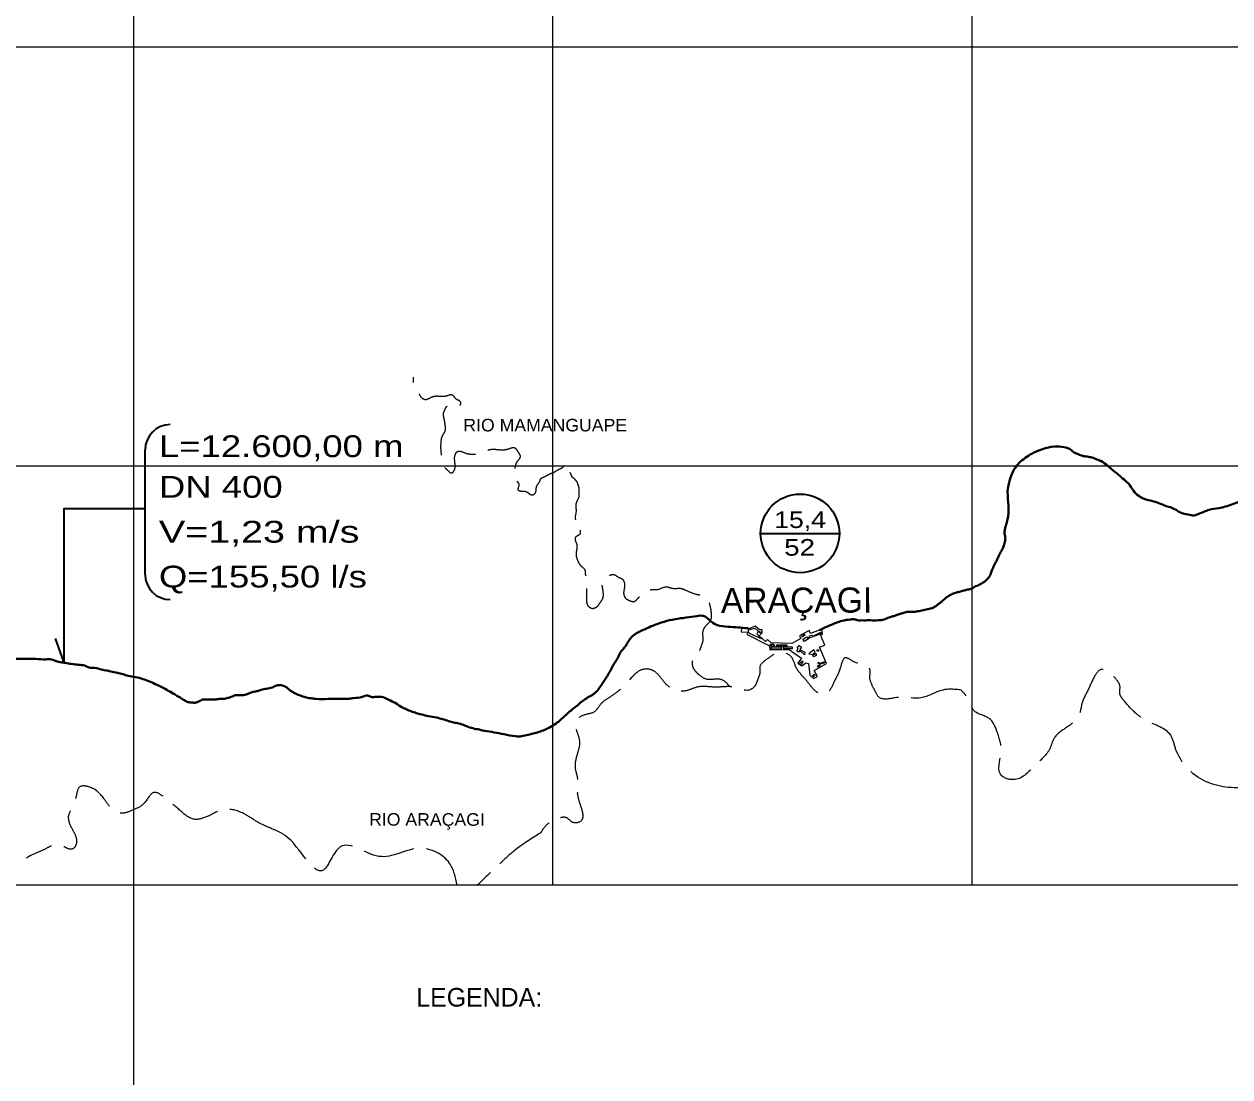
# Model space of a CAD drawing. Extents: x 0 to 1772, y 0 to 1188.
# Drawn here: x 598.6 to 781.9, y 161 to 321.1 of the extents above; entities that cross this region are included whole.
import ezdxf
from ezdxf.enums import TextEntityAlignment as Align

# ---------------------------------------------------------------- set-up
doc = ezdxf.new("R2010")
doc.units = 0
doc.header["$LTSCALE"] = 1.3
doc.linetypes.add('DOT_DASHED', pattern=[7.7, 5, -1.2, 0.3, -1.2])
doc.linetypes.add('LONG_DASHED', pattern=[7.5, 6, -1.5])
for name, color, linetype, lineweight in [('1', 7, 'DOT_DASHED', 13), ('5', 7, 'LONG_DASHED', 25), ('6', 7, 'Continuous', 40), ('63', 7, 'Continuous', 25), ('8', 7, 'Continuous', 35), ('9', 7, 'Continuous', 40)]:
    doc.layers.add(name, color=color, linetype=linetype, lineweight=lineweight)

msp = doc.modelspace()

# ---------------------------------------------------------------- linework, layer by layer
at = {"layer": '1', "linetype": 'Continuous'}
for points in [[(720.533, 223.884), (719.503, 226.352), (720.286, 226.679), (719.65, 228.204), (719.93, 228.321), (719.842, 229.095), (718.089, 228.414), (717.909, 228.876), (716.432, 228.061), (716.644, 227.677), (715.289, 226.93), (712.115, 227.006), (711.554, 227.526), (711.257, 227.205), (710.317, 228.077), (710.755, 228.55), (710.759, 228.971), (710.337, 228.975), (709.716, 229.547), (708.753, 229.12), (707.614, 229.213), (707.572, 228.692), (708.513, 228.615), (708.485, 228.274), (711.885, 226.561), (711.906, 225.924), (714.853, 226.022), (715.591, 225.51), (716.764, 224.695), (716.209, 223.896), (716.779, 223.501), (717.427, 223.971), (717.794, 223.876), (717.992, 222.119), (718.592, 221.58), (719.169, 221.891), (718.676, 222.809)], [(708.709, 228.614), (708.708, 228.97), (709.645, 229.26), (710.11, 228.816), (710.615, 228.581), (710.571, 228.487), (710.123, 228.697), (709.979, 228.39), (710.687, 227.622), (708.917, 228.398)], [(716.855, 227.902), (717.319, 228.183), (717.221, 228.345), (716.757, 228.064)], [(719.723, 228.403), (718.011, 227.773), (717.189, 227.212), (716.971, 227.531), (717.519, 227.905), (717.65, 227.712), (718.002, 227.952), (717.91, 228.086), (718.302, 228.186), (718.542, 228.094), (719.669, 228.615)], [(712.645, 226.501), (712.279, 226.5), (711.983, 226.657), (712.066, 226.815), (712.555, 226.797)], [(712.093, 226.104), (713.712, 226.109), (713.711, 226.346), (712.092, 226.341)], [(714.579, 226.675), (712.96, 226.67), (712.96, 226.482), (714.58, 226.487)], [(713.978, 226.159), (715.39, 226.164), (715.389, 226.341), (713.978, 226.337)], [(716.509, 225.867), (716.299, 225.589), (716.021, 225.798), (716.231, 226.077), (716.08, 226.19), (716.412, 226.631), (716.759, 226.37), (716.498, 226.023), (717.265, 225.611), (717.189, 225.199)], [(718.601, 225.959), (717.867, 225.364), (718.422, 225.232), (718.841, 225.587)], [(719.118, 225.75), (719.117, 225.964), (719.331, 225.965), (719.332, 225.751)], [(716.63, 223.677), (717.002, 224.051), (716.819, 224.232), (716.448, 223.858)], [(718.986, 225.08), (718.605, 224.869), (718.458, 225.133), (718.957, 225.409)], [(719.564, 223.58), (719.269, 223.33), (719.16, 223.459), (719.455, 223.709)], [(719.334, 223.771), (719.238, 223.962), (719.429, 224.058), (719.525, 223.867)], [(720.327, 224.032), (719.745, 223.753), (719.667, 223.915), (720.249, 224.194)], [(718.566, 221.865), (718.412, 222.036), (718.659, 222.257), (718.813, 222.085)]]:
    msp.add_lwpolyline(points, close=True, dxfattribs=at)
at = {"layer": '5'}
for points in [[(677.987, 252.401), (677.389, 252.097), (677.07, 251.93), (676.911, 251.53), (676.559, 250.992), (676.422, 250.712), (676.35, 250.134), (676.202, 249.707), (675.852, 249.458), (675.468, 249.581), (675.038, 249.89), (674.492, 250.041), (674.057, 250.04), (673.751, 250.173), (673.714, 250.548), (673.845, 251.107), (673.556, 251.51), (673.296, 251.966), (673.214, 252.781), (673.213, 253.141), (673.288, 253.972), (673.567, 254.593), (673.928, 255.067), (674.025, 255.41), (673.783, 255.866), (673.447, 256.403), (673.105, 256.643), (672.38, 256.527), (671.737, 256.353), (670.576, 256.35), (669.332, 256.346), (668.676, 256.114), (667.779, 255.843), (667.299, 255.657), (666.508, 255.655), (665.992, 255.724), (664.924, 256.08), (664.348, 256.003), (664.085, 255.656), (664.014, 254.461), (664.016, 253.477), (663.801, 253.021), (663.564, 252.79), (663.109, 253.094), (662.592, 253.615), (662.319, 254.28), (662.12, 255.135), (661.96, 256.268), (661.957, 257.415), (662.036, 258.101), (662.299, 258.699), (662.629, 259.379), (662.628, 259.815), (662.47, 260.869), (662.349, 261.98), (662.601, 262.566), (662.911, 263.036), (663.574, 263.037), (664.48, 263.04), (664.899, 263.227), (664.897, 263.662), (664.302, 264.035), (663.706, 264.657), (662.624, 264.498), (661.26, 264.494), (660.462, 264.316), (659.586, 263.972), (658.99, 264.302), (658.52, 265.027), (658.033, 265.706), (657.801, 266.239), (657.798, 267.405)], [(705.846, 220.321), (705.244, 221.014), (704.288, 221.478), (702.311, 221.472), (701.198, 222.136), (700.619, 222.713), (700.217, 223.445), (700.214, 224.357), (700.479, 225.047), (701.077, 225.516), (701.43, 226.273), (701.782, 227.408), (701.778, 228.72), (702.198, 229.589), (702.774, 230.191), (703.039, 230.725), (703.035, 231.748), (702.765, 232.97), (702.029, 233.991), (700.829, 234.343), (699.205, 234.961), (698.383, 235.248), (697.228, 235.244), (696.25, 235.486), (694.696, 235.059), (693.874, 235.056), (692.553, 234.305), (691.808, 233.71), (691.397, 233.296), (690.559, 233.422), (690.095, 233.692), (689.757, 234.568), (689.896, 235.728), (689.636, 236.579), (688.797, 237.028), (688.358, 237.323), (687.457, 237.165), (686.982, 236.79), (686.455, 236.249), (686.458, 235.44), (686.56, 234.668), (686.562, 233.986), (686.355, 233.467), (685.993, 232.948), (685.704, 232.529), (685.368, 232.301), (684.906, 232.208), (684.542, 232.398), (684.214, 232.834), (684.121, 233.588), (684.118, 234.551), (684.115, 235.379), (684.112, 236.588), (684.019, 237.151), (683.909, 237.487), (683.908, 237.923), (683.434, 238.522), (682.951, 239.093), (682.668, 239.756), (682.53, 240.282), (682.627, 241.274), (682.625, 241.989), (682.405, 242.571), (682.48, 243.148), (683.087, 243.573), (683.084, 244.669), (683.082, 245.38), (682.511, 245.673), (682.508, 246.839), (682.504, 248.092), (682.72, 248.718), (682.947, 249.251), (682.945, 249.84), (682.943, 250.533), (682.831, 250.929), (682.675, 251.393), (682.439, 251.715), (682.116, 252.048), (681.942, 252.165), (681.753, 252.546), (681.564, 252.96), (681.43, 253.319), (681.149, 253.646), (681.071, 253.974), (681.02, 254.197), (680.673, 253.957), (680.417, 253.663), (679.759, 253.309), (679.161, 252.936), (678.517, 252.677), (677.987, 252.401)], [(878.537, 228.689), (877.747, 230.803), (877.216, 232.856), (877.212, 234.145), (875.304, 234.14), (873.443, 234.134), (870.863, 235.13), (868.856, 236.127), (866.699, 235.399), (864.745, 233.881), (862.487, 231.228), (860.772, 228.743), (859.528, 226.282), (858.189, 224.317), (856.519, 222.611), (851.453, 222.861), (846.687, 222.847), (842.65, 222.567), (841.119, 222.222), (837.914, 222.032), (836.297, 223.062), (835.291, 226.072), (833.291, 228.044), (831.386, 228.438), (828.195, 227.04), (824.327, 224.014), (819.287, 222.831), (815.491, 221.162), (811.543, 219.831), (808.084, 218.691), (805.568, 216.724), (803.353, 214.682), (799.83, 212.067), (792.437, 207.269), (784.559, 205.048), (778.069, 205.977), (773.613, 210.91), (772.858, 212.956), (769.159, 215.193), (767.459, 216.387), (765.657, 218.341), (765.141, 219.205), (765.137, 220.503), (764.513, 221.529), (763.51, 222.554), (762.293, 222.956), (761.377, 222.061), (760.33, 219.921), (759.364, 217.782), (758.883, 215.941), (756.997, 214.123), (755.138, 212.495), (754.521, 211.006), (752.137, 208.282), (749.213, 206.239), (747.084, 206.895), (747.074, 210.443), (746.498, 213.422), (745.215, 215.548), (743.038, 216.629), (742.088, 218.424), (740.996, 219.84)], [(740.996, 219.84), (738.208, 219.832), (735.092, 218.687), (731.17, 218.676), (728.618, 218.668), (727.763, 220.038), (727.144, 221.644), (727.14, 222.969), (724.679, 224.145), (723.375, 224.745), (722.589, 223.019), (721.642, 220.967), (720.832, 219.568), (720.042, 219.193), (718.598, 219.934), (717.384, 221.42), (715.96, 223.209), (715.071, 224.999), (713.534, 225.577), (711.653, 224.64), (710.401, 223.309), (710.403, 222.448), (710.058, 221.375), (709.711, 220.536), (708.946, 219.882), (706.188, 220.322), (704.851, 220.318), (702.904, 220.313), (700.981, 220.307), (699.387, 219.762), (697.652, 219.757), (696.406, 220.481), (695.088, 222.027), (693.983, 222.893), (692.388, 222.888), (690.984, 221.804), (689.18, 219.93), (687.705, 218.825), (686.419, 217.892), (685.192, 216.484), (683.412, 215.929), (682.448, 214.958), (682.719, 213.157), (683.007, 211.849), (682.727, 210.349), (682.39, 209.02), (682.394, 207.654), (682.663, 206.611), (682.67, 204.126)], [(636.92, 198.473), (633.928, 199.847), (631.933, 201.062), (628.912, 201.664), (626.538, 200.661), (624.355, 200.204), (622.167, 201.644), (620.01, 203.407), (618.369, 204.27), (616.833, 202.626), (615.021, 201.547), (613.372, 201.101), (611.94, 201.785), (610.698, 203.351), (608.465, 205.106), (607.035, 205.102), (606.517, 203.751), (605.89, 201.932), (605.316, 200.692), (605.816, 198.849), (606.481, 197.392), (606.484, 196.345), (605.881, 195.655), (605.445, 195.654), (604.449, 196.147), (602.799, 196.142), (601.426, 195.477), (599.586, 194.673), (598.927, 194.286)], [(682.67, 204.126), (682.896, 203.042), (683.462, 201.108), (683.325, 200.038), (681.888, 199.754), (681.059, 200.401), (680.004, 200.398), (678.581, 199.795), (677.617, 198.901), (677.098, 198.11)], [(664.393, 190.159), (663.21, 193.551), (658.657, 195.771), (652.484, 194.55), (646.646, 195.993), (644.083, 192.464), (638.319, 197.686), (636.705, 198.571)], [(677.098, 198.11), (673.071, 195.384), (670.589, 193.144), (667.447, 190.159)]]:
    msp.add_spline(points, degree=3, dxfattribs=at)
at = {"layer": '6'}
msp.add_line((708.6, 229.235), (708.753, 229.12), dxfattribs=at)
for points in [[(768.53, 249.042), (767.996, 249.362), (767.198, 250.166), (766.419, 251.264), (765.547, 252.008), (764.706, 252.758), (764.06, 253.243), (763.236, 253.967), (762.239, 254.659), (761.842, 254.83), (761.059, 255.116), (760.371, 255.291), (759.539, 255.413), (758.717, 255.724), (758.05, 256.046), (757.463, 256.506), (756.941, 256.698), (755.577, 256.877), (753.845, 256.601), (752.985, 256.326), (751.77, 255.768), (750.763, 255.128), (749.833, 254.361), (749.087, 253.409), (748.577, 252.243), (748.12, 250.51), (748.133, 246.229), (747.929, 245.347), (747.751, 244.632), (747.626, 244.105), (747.628, 243.419), (747.72, 243.024), (747.721, 242.667), (747.655, 242.376), (747.563, 241.942), (747.446, 241.633), (747.221, 241.205), (746.827, 240.449), (746.543, 239.818), (746.297, 239.323), (745.999, 238.741), (745.734, 238.137), (745.507, 237.579), (745.386, 237.218), (745.235, 237.016), (745.1, 236.796), (744.966, 236.672), (744.74, 236.499), (744.561, 236.295), (744.18, 236.092), (743.872, 235.888), (743.545, 235.743), (743.446, 235.665), (743.421, 235.665), (742.632, 235.253), (741.985, 235.099), (741.383, 234.946), (740.738, 234.78), (740.137, 234.596), (739.558, 234.377), (738.971, 234.049), (738.522, 233.707), (738.071, 233.319), (737.731, 233.027), (737.347, 232.75), (736.934, 232.469), (736.525, 232.263), (736.173, 232.167), (735.25, 231.972), (734.433, 231.806), (733.635, 231.708), (732.744, 231.705), (732.175, 231.544), (731.652, 231.38), (731.172, 231.234), (730.62, 231.042), (730.089, 230.869), (729.293, 230.576), (728.383, 230.438), (727.239, 230.434), (726.224, 230.431), (725.714, 230.43), (725.434, 230.429), (724.795, 230.569), (724.179, 230.567), (722.926, 230.356), (722.018, 230.059), (721.486, 229.846), (720.689, 229.515), (719.473, 228.956)], [(810.477, 247.81), (809.84, 247.46), (809.386, 247.225), (808.978, 247.05), (808.438, 247.048), (807.594, 247.192), (806.798, 247.472), (806.374, 247.698), (805.659, 248.129), (804.633, 248.527), (803.328, 248.523), (802.525, 248.08), (801.635, 248.078), (800.638, 247.949), (799.642, 248.075), (798.524, 248.394), (797.915, 248.392), (796.704, 248.388), (795.318, 248.384), (794.258, 248.579), (793.233, 248.775), (792.845, 248.956), (792.282, 249.217), (791.253, 249.214), (789.639, 248.883), (788.152, 248.652), (786.834, 248.471), (784.889, 248.621), (783.377, 248.478), (781.147, 247.722), (780.179, 247.501), (778.702, 247.222), (777.052, 246.584), (776.405, 246.395), (775.484, 246.519), (774.335, 246.824), (773.451, 247.357), (772.185, 247.813), (771.049, 248.239), (769.981, 248.592), (768.996, 248.832), (768.419, 249.061)], [(708.6, 229.235), (705.572, 229.469), (703.95, 229.714), (703.5, 229.905), (702.682, 230.553), (701.869, 231.092), (700.838, 231.089), (699.225, 230.853), (697.067, 230.528), (695.45, 230.101), (693.266, 229.242), (691.684, 228.456), (690.892, 227.851), (690.362, 227.115), (690.068, 226.611), (689.747, 226.18), (689.241, 225.573), (688.82, 224.746), (688.402, 224.06), (687.979, 223.308), (687.528, 222.497), (687.064, 221.718), (686.65, 221.077), (686.109, 220.277), (685.602, 219.634), (685.251, 219.299), (684.826, 219.013), (684.045, 218.568), (683.296, 218.018), (682.542, 217.405), (682.01, 216.984), (681.338, 216.398), (680.72, 215.844), (680.125, 215.299), (679.431, 214.747), (678.559, 214.195), (677.708, 213.776), (676.824, 213.458), (675.95, 213.204), (675.211, 213.03), (674.181, 212.812), (673.331, 212.81), (671.488, 213.12), (670.02, 213.394), (668.572, 213.651), (667.563, 213.862), (666.566, 214.08), (665.59, 214.452), (664.662, 214.747), (663.863, 214.902), (663.105, 215.123)], [(663.116, 215.118), (661.289, 215.641), (660.048, 215.863), (659.006, 216.112), (658.198, 216.343), (657.443, 216.586), (656.666, 216.919), (655.886, 217.281), (654.984, 217.867), (654.041, 218.336), (653.166, 218.727), (652.089, 218.802), (651.323, 218.8), (650.816, 218.995), (649.955, 218.79), (648.703, 218.612), (647.936, 218.501), (646.919, 218.498), (644.822, 218.492), (642.899, 218.486), (642.369, 218.571), (641.485, 218.681), (640.779, 218.917), (640.03, 219.205), (639.595, 219.425), (639.09, 219.725), (638.675, 220.069), (637.953, 220.489), (636.859, 220.486), (636.297, 220.228), (635.43, 220.034), (634.612, 219.844), (634.04, 219.673), (633.513, 219.572), (632.948, 219.404), (632.497, 219.232), (632.149, 219.112), (631.755, 219.041), (630.728, 219.038), (630.075, 218.807), (629.545, 218.625), (628.928, 218.486), (628.236, 218.484), (627.594, 218.38), (626.998, 218.378), (626.56, 218.377), (625.754, 218.375), (625.126, 218.116), (624.667, 217.932), (624.057, 217.93), (623.457, 218.006), (622.94, 218.28), (622.082, 218.814), (620.963, 219.454), (620.033, 220.005), (618.815, 220.611), (617.658, 221.132), (616.646, 221.509), (615.533, 221.807), (614.421, 221.997), (613.585, 222.244), (612.755, 222.426), (611.785, 222.647), (610.989, 222.825), (610.092, 223.02), (609.027, 223.211), (608.625, 223.209), (608.338, 223.312), (607.773, 223.543), (606.864, 223.674), (605.805, 223.801), (604.818, 223.947), (604.167, 224.058), (603.466, 224.224), (602.757, 224.491), (601.886, 224.488), (600.366, 224.565), (598.487, 224.559), (597.737, 224.557), (593.675, 224.545), (591.66, 224.406), (588.722, 224.398), (585.098, 224.387), (583.191, 224.548), (581.41, 224.688)]]:
    msp.add_spline(points, degree=3, dxfattribs=at)
at = {"layer": '63', "lineweight": 13}
for p, q in [((615.246, 62.735), (615.246, 419.523)), ((678.959, 190.159), (678.959, 419.523)), ((742.671, 190.159), (742.671, 419.523)), ((1175.913, 317.583), (487.822, 317.583)), ((1175.913, 253.871), (487.822, 253.871)), ((1175.913, 190.159), (487.822, 190.159))]:
    msp.add_line(p, q, dxfattribs=at)
at = {"layer": '8'}
msp.add_line((616.976, 237.402), (616.976, 256.358), dxfattribs=at)
msp.add_lwpolyline([(616.976, 247.359), (604.627, 247.359), (604.627, 224.123), (603.36, 227.69)], dxfattribs=at)
for centre, start, end in [((620.799, 256.358), 90, 180), ((620.799, 256.358), 90, 180), ((620.799, 256.358), 90, 180), ((620.799, 237.402), 180, 270)]:
    msp.add_arc(centre, 3.823, start, end, dxfattribs=at)
at = {"layer": '9', "lineweight": 35}
msp.add_line((710.536, 243.65), (722.506, 243.65), dxfattribs=at)
msp.add_circle((716.521, 243.65), 5.985, dxfattribs=at)

# ---------------------------------------------------------------- texts
at = {"layer": '5', "width": 1.05}
for s, rotation, p in [('RIO MAMANGUAPE', 0.006, (665.343, 259.153)), ('RIO ARAÇAGI', 359.911, (651.016, 199.219))]:
    msp.add_text(s, height=1.911, rotation=rotation, dxfattribs=at).set_placement(p)
at = {"layer": '63'}
msp.add_text('LEGENDA:', height=2.829, dxfattribs=at).set_placement((658.192, 171.708))
at = {"layer": '8'}
for s, width, p in [('L=12.600,00 m', 1.25, (619.074, 255.245)), ('DN 400', 1.25, (619.074, 249.065)), ('V=1,23 m/s', 1.35, (619.074, 242.241)), ('Q=155,50 l/s', 1.25, (619.074, 235.418))]:
    msp.add_text(s, height=3.319, dxfattribs=dict(at, width=width)).set_placement(p)
at = {"layer": '9'}
for s, width, p in [('15,4', 1.2, (716.531, 244.471)), ('52', 1.25, (716.457, 240.267))]:
    msp.add_text(s, height=2.52, rotation=0.17, dxfattribs=dict(at, width=width)).set_placement(p, align=Align.CENTER)
msp.add_text('ARAÇAGI', height=3.823, rotation=0.17, dxfattribs=at).set_placement((704.494, 231.541))

doc.saveas('drawing.dxf')
